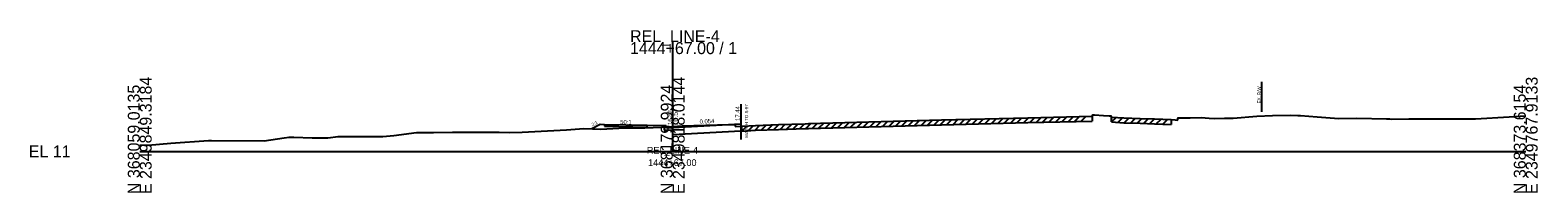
# Model space of a CAD drawing. Extents: x -26 to 2350146, y -10 to 368200.
# Drawn here: x 1974.3 to 2327.8, y 4990.3 to 5028.4 of the extents above; entities that cross this region are included whole.
import ezdxf

# ---------------------------------------------------------------- set-up
doc = ezdxf.new("R2010")
doc.units = 0
for name, color, linetype in [('RD_GPK_XS_Cell', 7, 'Continuous'), ('RD_XS_Base', 7, 'Continuous'), ('RD_XS_CurbBase', 7, 'Continuous'), ('RD_XS_CurbFront', 7, 'Continuous'), ('RD_XS_CurbTop', 7, 'Continuous'), ('RD_XS_EarthShd', 7, 'Continuous'), ('RD_XS_ExGround', 7, 'Continuous'), ('RD_XS_ExPaveRet', 7, 'Continuous'), ('RD_XS_ExRW', 7, 'Continuous'), ('RD_XS_Pave', 7, 'Continuous'), ('RD_XS_SW', 7, 'Continuous'), ('RD_XS_SWbase', 7, 'Continuous'), ('RD_XS_TieSlope', 7, 'Continuous'), ('RD_XS_TX_Elev_EX', 7, 'Continuous'), ('RD_XS_TX_Elev_PR', 7, 'Continuous'), ('RD_XS_TX_MatchLine', 7, 'Continuous'), ('RD_XS_TX_Slope', 7, 'Continuous'), ('RD_XS_TX_Station', 7, 'Continuous'), ('RD_XS_TX_TOC', 7, 'Continuous')]:
    doc.layers.add(name, color=color, linetype=linetype)

msp = doc.modelspace()

# ---------------------------------------------------------------- linework, layer by layer
at = {"layer": 'RD_GPK_XS_Cell'}
for p, q in [((2124.96, 5000), (2124.96, 5025.58)), ((2000, 5000), (2124.96, 5000)), ((2124.96, 5000), (2324.96, 5000))]:
    msp.add_line(p, q, dxfattribs=at)
at = {"layer": 'RD_XS_Base'}
msp.add_line((2124.96, 5003.93), (2140.96, 5004.8), dxfattribs=at)
at = {"layer": 'RD_XS_CurbBase'}
for p, q in [((2122.96, 5005.97), (2122.96, 5004.97)), ((2122.96, 5004.97), (2123.46, 5004.97)), ((2123.46, 5004.97), (2124.96, 5005.05)), ((2124.96, 5003.93), (2124.96, 5005.05))]:
    msp.add_line(p, q, dxfattribs=at)
at = {"layer": 'RD_XS_CurbFront'}
msp.add_line((2124.96, 5005.05), (2124.96, 5005.55), dxfattribs=at)
at = {"layer": 'RD_XS_CurbTop'}
for p, q in [((2123.46, 5005.97), (2122.96, 5005.97)), ((2123.55, 5005.47), (2123.46, 5005.97)), ((2124.96, 5005.55), (2123.55, 5005.47)), ((2124.96, 5005.57), (2124.96, 5005.55))]:
    msp.add_line(p, q, dxfattribs=at)
at = {"layer": 'RD_XS_EarthShd'}
for p, q in [((2108.96, 5006.25), (2107.96, 5006.27)), ((2122.96, 5005.97), (2118.96, 5006.05))]:
    msp.add_line(p, q, dxfattribs=at)
at = {"layer": 'RD_XS_ExGround'}
msp.add_lwpolyline([(2000, 5001.51), (2001.15, 5001.49), (2002, 5001.47), (2007.3, 5001.89), (2016.15, 5002.54), (2016.85, 5002.54), (2029.15, 5002.48), (2033.86, 5003.14), (2035.01, 5003.33), (2036.13, 5003.33), (2040.45, 5003.14), (2044.09, 5003.18), (2046.54, 5003.51), (2050.7, 5003.51), (2057.01, 5003.5), (2059.56, 5003.74), (2064.9, 5004.4), (2068.9, 5004.42), (2073.37, 5004.5), (2076.81, 5004.5), (2081.61, 5004.5), (2084.31, 5004.49), (2086.74, 5004.44), (2089.68, 5004.49), (2100.03, 5005.04), (2104.1, 5005.4), (2108.13, 5005.18), (2113.73, 5005.49), (2118.44, 5005.53), (2122.34, 5005.64), (2124.96, 5005.82), (2127.21, 5005.98), (2138.2, 5006.33), (2139.02, 5006.32), (2139.52, 5006.32), (2139.68, 5005.82), (2141.18, 5005.91), (2144.35, 5006.08), (2149.8, 5006.29), (2156.04, 5006.49), (2156.79, 5006.51), (2187.97, 5007.37), (2208.21, 5007.88), (2223.33, 5008.23), (2223.49, 5008.53), (2223.85, 5008.53), (2225.99, 5008.44), (2227.32, 5008.34), (2227.68, 5008.34), (2227.84, 5008.04), (2230.77, 5007.86), (2234.56, 5007.72), (2237.89, 5007.61), (2241.8, 5007.47), (2242.76, 5007.37), (2243.32, 5007.34), (2243.49, 5007.84), (2243.99, 5007.84), (2246.28, 5007.88), (2248.85, 5007.94), (2250.74, 5007.78), (2252.1, 5007.72), (2254.33, 5007.81), (2256.33, 5007.81), (2261.92, 5008.25), (2265.58, 5008.38), (2269.71, 5008.46), (2271.51, 5008.41), (2272.15, 5008.38), (2276.06, 5008.07), (2281.14, 5007.7), (2285.35, 5007.77), (2292.33, 5007.61), (2293.06, 5007.59), (2293.39, 5007.58), (2297.59, 5007.65), (2303.86, 5007.63), (2307.42, 5007.65), (2313.21, 5007.6), (2314.51, 5007.7), (2324.96, 5008.36)], dxfattribs=at)
at = {"layer": 'RD_XS_ExPaveRet'}
for p, q in [((2141.18, 5004.76), (2142.39, 5005.97)), ((2141.18, 5004.76), (2141.18, 5005.91)), ((2142.68, 5004.85), (2143.89, 5006.05)), ((2144.18, 5004.93), (2145.37, 5006.12)), ((2145.68, 5004.99), (2146.87, 5006.18)), ((2147.18, 5005.05), (2148.37, 5006.23)), ((2148.68, 5005.1), (2149.87, 5006.29)), ((2150.18, 5005.16), (2151.36, 5006.34)), ((2151.68, 5005.21), (2152.86, 5006.39)), ((2153.18, 5005.26), (2154.36, 5006.44)), ((2154.68, 5005.3), (2155.86, 5006.48)), ((2156.18, 5005.35), (2157.36, 5006.53)), ((2156.79, 5005.37), (2187.97, 5006.22)), ((2157.68, 5005.39), (2158.86, 5006.57)), ((2159.18, 5005.43), (2160.36, 5006.61)), ((2160.68, 5005.47), (2161.86, 5006.65)), ((2162.18, 5005.52), (2163.36, 5006.69)), ((2163.68, 5005.56), (2164.86, 5006.73)), ((2165.18, 5005.6), (2166.36, 5006.77)), ((2166.68, 5005.64), (2167.86, 5006.81)), ((2168.18, 5005.68), (2169.36, 5006.86)), ((2169.68, 5005.72), (2170.86, 5006.9)), ((2171.18, 5005.76), (2172.36, 5006.94)), ((2172.68, 5005.8), (2173.86, 5006.98)), ((2174.18, 5005.84), (2175.36, 5007.02)), ((2175.68, 5005.89), (2176.86, 5007.06)), ((2177.18, 5005.93), (2178.36, 5007.1)), ((2178.68, 5005.97), (2179.86, 5007.14)), ((2180.18, 5006.01), (2181.36, 5007.18)), ((2181.68, 5006.05), (2182.86, 5007.23)), ((2183.18, 5006.09), (2184.36, 5007.27)), ((2184.68, 5006.13), (2185.86, 5007.31)), ((2186.18, 5006.17), (2187.36, 5007.35)), ((2187.68, 5006.22), (2188.85, 5007.39)), ((2187.97, 5006.22), (2208.21, 5006.73)), ((2189.18, 5006.25), (2190.35, 5007.43)), ((2190.68, 5006.29), (2191.85, 5007.46)), ((2192.18, 5006.33), (2193.35, 5007.5)), ((2193.68, 5006.37), (2194.85, 5007.54)), ((2195.18, 5006.41), (2196.35, 5007.58)), ((2196.68, 5006.44), (2197.85, 5007.62)), ((2198.18, 5006.48), (2199.35, 5007.65)), ((2199.68, 5006.52), (2200.85, 5007.69)), ((2201.18, 5006.56), (2202.35, 5007.73)), ((2202.68, 5006.59), (2203.85, 5007.77)), ((2204.18, 5006.63), (2205.35, 5007.8)), ((2205.68, 5006.67), (2206.85, 5007.84)), ((2207.18, 5006.71), (2208.35, 5007.88)), ((2208.21, 5006.73), (2223.33, 5007.08)), ((2208.68, 5006.74), (2209.85, 5007.92)), ((2210.18, 5006.78), (2211.35, 5007.95)), ((2211.68, 5006.81), (2212.85, 5007.98)), ((2213.18, 5006.85), (2214.35, 5008.02)), ((2214.68, 5006.88), (2215.85, 5008.05)), ((2216.18, 5006.92), (2217.35, 5008.09)), ((2217.68, 5006.95), (2218.85, 5008.12)), ((2219.18, 5006.99), (2220.35, 5008.16)), ((2220.68, 5007.02), (2221.85, 5008.19)), ((2223.33, 5008.23), (2223.33, 5007.08)), ((2227.84, 5006.89), (2227.84, 5008.04)), ((2227.84, 5006.89), (2228.92, 5007.97)), ((2227.84, 5006.89), (2230.77, 5006.72)), ((2229.34, 5006.8), (2230.42, 5007.88)), ((2230.77, 5006.72), (2234.56, 5006.58)), ((2230.84, 5006.72), (2231.94, 5007.82)), ((2232.34, 5006.66), (2233.44, 5007.76)), ((2233.84, 5006.61), (2234.94, 5007.71)), ((2234.56, 5006.58), (2237.89, 5006.46)), ((2235.34, 5006.55), (2236.44, 5007.66)), ((2236.84, 5006.5), (2237.94, 5007.61)), ((2237.89, 5006.46), (2241.8, 5006.33)), ((2238.34, 5006.45), (2239.45, 5007.55)), ((2239.84, 5006.4), (2240.95, 5007.5)), ((2241.8, 5007.47), (2241.8, 5006.33)), ((2141.18, 5004.76), (2144.35, 5004.94)), ((2144.35, 5004.94), (2149.8, 5005.15)), ((2149.8, 5005.15), (2156.04, 5005.35)), ((2156.04, 5005.35), (2156.79, 5005.37))]:
    msp.add_line(p, q, dxfattribs=at)
at = {"layer": 'RD_XS_ExRW'}
msp.add_line((2263.07, 5009.29), (2263.07, 5016.29), dxfattribs=at)
at = {"layer": 'RD_XS_Pave'}
for p, q in [((2140.96, 5011.09), (2140.96, 5002.82)), ((2124.96, 5005.57), (2140.96, 5006.44))]:
    msp.add_line(p, q, dxfattribs=at)
at = {"layer": 'RD_XS_SW'}
msp.add_line((2118.96, 5006.05), (2108.96, 5006.25), dxfattribs=at)
at = {"layer": 'RD_XS_SWbase'}
for p, q in [((2108.96, 5006.25), (2108.96, 5005.91)), ((2108.96, 5005.91), (2118.96, 5005.71)), ((2118.96, 5005.71), (2118.96, 5006.05))]:
    msp.add_line(p, q, dxfattribs=at)
at = {"layer": 'RD_XS_TieSlope'}
msp.add_line((2107.96, 5006.27), (2106.01, 5005.29), dxfattribs=at)

# ---------------------------------------------------------------- texts
at = {"layer": 'RD_GPK_XS_Cell'}
for s, p in [('REL_LINE-4', (2114.96, 5025.58)), ('1444+67.00 / 1', (2114.96, 5022.78)), ('EL 11', (1974, 4998.6))]:
    msp.add_text(s, height=2.8, dxfattribs=at).set_placement(p)
for s, p in [('E 2349849.3184', (2002.8, 4990)), ('E 2349818.0144', (2127.76, 4990)), ('E 2349767.9133', (2327.76, 4990)), ('N 368059.0135', (2000, 4990)), ('N 368179.9924', (2124.96, 4990)), ('N 368373.6154', (2324.96, 4990))]:
    msp.add_text(s, height=2.8, rotation=90, dxfattribs=at).set_placement(p)
at = {"layer": 'RD_XS_ExRW'}
msp.add_text('EX. R/W ', height=0.75, rotation=90, dxfattribs=at).set_placement((2262.82, 5011.25))
at = {"layer": 'RD_XS_TX_Elev_EX'}
msp.add_text('16.82', height=1, rotation=90, dxfattribs=at).set_placement((2124.81, 5006.2))
at = {"layer": 'RD_XS_TX_Elev_PR'}
for s, height, rotation, p in [(' 16.57', 1.2, 90, (2126.16, 5005.57)), ('17.44', 1, 90, (2140.66, 5007.15)), ('50:1', 1, 358.8542, (2112.64, 5006.38)), ('0.054', 1, 3.1024, (2131.29, 5006.46))]:
    msp.add_text(s, height=height, rotation=rotation, dxfattribs=at).set_placement(p)
at = {"layer": 'RD_XS_TX_MatchLine'}
msp.add_text('MATCH TO S-97', height=0.75, rotation=90, dxfattribs=at).set_placement((2142.65, 5003.18))
at = {"layer": 'RD_XS_TX_Slope'}
msp.add_text('2:1', height=0.75, rotation=26.5651, dxfattribs=at).set_placement((2106.19, 5005.87))
at = {"layer": 'RD_XS_TX_Station'}
for s, p in [('REL_LINE-4', (2118.89, 4999.47)), ('1444+67.00', (2119.19, 4996.57))]:
    msp.add_text(s, height=1.6, dxfattribs=at).set_placement(p)
at = {"layer": 'RD_XS_TX_TOC'}
msp.add_text('TOCLT', height=0.05, dxfattribs=at).set_placement((2123.51, 5005.92))

doc.saveas('drawing.dxf')
